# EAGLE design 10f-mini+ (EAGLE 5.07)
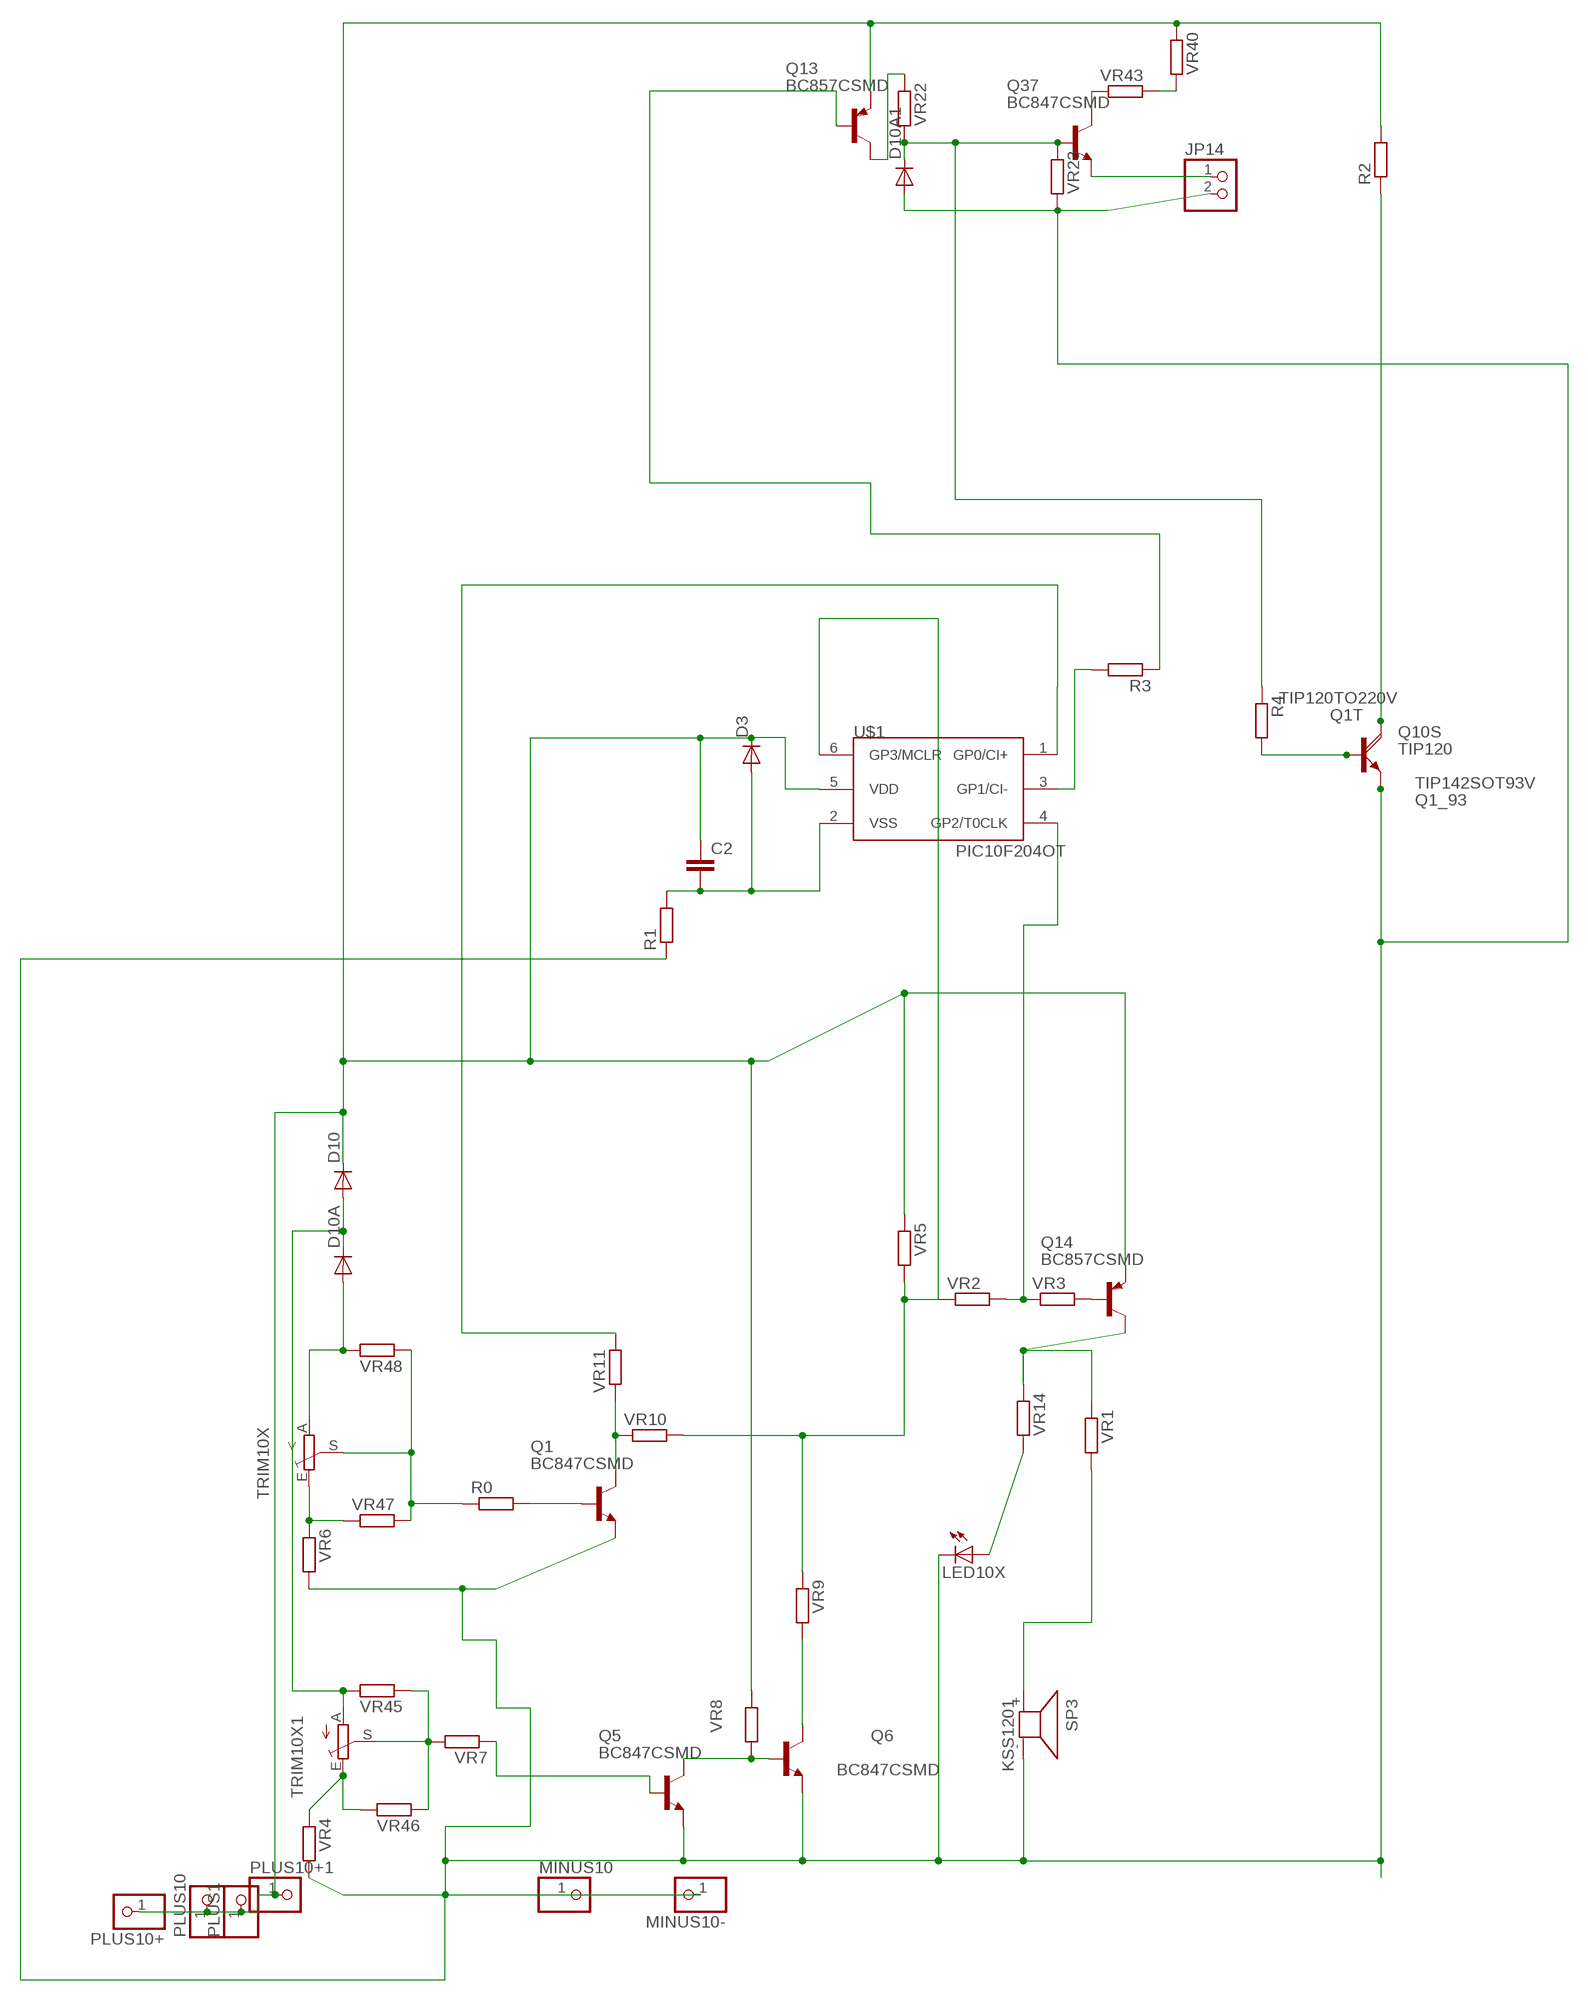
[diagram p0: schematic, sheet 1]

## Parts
C2  C-EUC0805  [C0805]
D3  DIODE-MINIMELF  [MINIMELF]
D10  DIODE-MINIMELF  [MINIMELF]
D10A  DIODE-MINIMELF  [MINIMELF]
D10A1  DIODE-MINIMELF  [MINIMELF]
JP14  PINHD-1X2STR  [1X02]
LED10X  LEDCHIPLED_1206  [CHIPLED_1206]
MINUS10  PINHD-1X14.5MM  [1X4MM5]
MINUS10-  PINHD-1X11X0.4  [1X01]
PLUS1  PINHD-1X14.5MM  [1X4MM5]
PLUS10  PINHD-1X14.5MM  [1X4MM5]
PLUS10+  PINHD-1X11X0.4  [1X01]
PLUS10+1  PINHD-1X11X0.4  [1X01]
Q1  BC847CSMD  [SOT23]
Q1_93  TIP142SOT93V  [SOT93V]
Q1T  TIP120TO220V  [TO220AV]
Q5  BC847CSMD  [SOT23]
Q6  BC847CSMD  [SOT23]
Q10S  TIP120  TIP120DPAK  [D-PAK_TO252AA]
Q13  BC857CSMD  [SOT23-BEC]
Q14  BC857CSMD  [SOT23-BEC]
Q37  BC847CSMD  [SOT23]
R0  R-EU_R1206  [R1206]
R1  R-EU_R0805  [R0805]
R2  R-EU_CERAM85  [CERAM85]
R3  R-EU_R0805  [R0805]
R4  R-EU_R0805  [R0805]
SP3  KSS1201  KSS12017MM  [KSS1202]
TRIM10X  TRIM_EU-S64W  [S64W]
TRIM10X1  TRIM_EU-S64W  [S64W]
U$1  PIC10F204OT  [SOT23-6]
VR1  R-EU_R0805  [R0805]
VR2  R-EU_R0805  [R0805]
VR3  R-EU_R1206  [R1206]
VR4  R-EU_R1206  [R1206]
VR5  R-EU_R0805  [R0805]
VR6  R-EU_R1206  [R1206]
VR7  R-EU_M1206  [M1206]
VR8  R-EU_R1206  [R1206]
VR9  R-EU_R0805  [R0805]
VR10  R-EU_R1206  [R1206]
VR11  R-EU_R0805  [R0805]
VR14  R-EU_R0805  [R0805]
VR22  R-EU_R0805  [R0805]
VR23  R-EU_R0805  [R0805]
VR40  R-EU_R1206  [R1206]
VR43  R-EU_R1206  [R1206]
VR45  R-EU_R0805  [R0805]
VR46  R-EU_R1206  [R1206]
VR47  R-EU_R0805  [R0805]
VR48  R-EU_R0805  [R0805]

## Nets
B: R0.1 TRIM10X.S VR47.2 VR48.1
BUZZ+: SP3.+ VR1.2
GP3: U$1.4(GP2/T0CLK) VR2.2 VR3.1
N$1: R3.2 U$1.3(GP1/CI-)
N$2: Q1.3(C) VR10.1 VR11.1
N$3: Q5.3(C) Q6.1(B) VR8.2
N$4: LED10X.A VR14.2
N$5: Q6.3(C) VR9.2
N$6: U$1.6(GP3/MCLR) VR2.1 VR5.2 VR9.1 VR10.2
N$7: Q1.1(B) R0.2
N$8: Q14.C VR1.1 VR14.1
N$10: Q14.B VR3.2
N$14: D10A.A TRIM10X.A VR48.2
N$17: D10.A D10A.C TRIM10X1.A VR45.2
N$22: TRIM10X1.S VR7.2 VR45.1 VR46.1
N$23: Q13.B R3.1
N$24: TRIM10X1.E VR4.1 VR46.2
N$25: Q1_93.B Q1T.B Q10S.1(B) R4.2
N$128: TRIM10X.E VR6.1 VR47.1
N$136: JP14.1 Q37.2(E)
N$138: U$1.1(GP0/CI+) VR11.2
N$159: Q13.C VR22.1
N$163: VR40.2 VR43.2
N$164: Q37.3(C) VR43.1
N$168: Q5.1(B) VR7.1
N$179: D10A1.C Q37.1(B) R4.1 VR22.2 VR23.1
PLUS1: C2.1 D3.C D10.C PLUS1.1 PLUS10+1.1 PLUS10+.1 PLUS10.1 Q13.E Q14.E R2.2 U$1.5(VDD) VR5.1 VR8.1 VR40.1
Q10C: Q1_93.C Q1T.C Q10S.4(C) R2.1
VSS: D10A1.A JP14.2 LED10X.C MINUS10-.1 MINUS10.1 Q1.2(E) Q1_93.E Q1T.E Q5.2(E) Q6.2(E) Q10S.3(E) R1.1 SP3.- VR4.2 VR6.2 VR23.2
VSS1: C2.2 D3.A R1.2 U$1.2(VSS)

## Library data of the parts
C2 = rcl:C-EU: CAPACITOR, European symbol
D3 D10 D10A D10A1 = diode:DIODE-: DIODE
JP14 = pinhead:PINHD-1X2: PIN HEADER
LED10X = led:LED: LED
MINUS10 MINUS10- PLUS1 PLUS10 PLUS10+ PLUS10+1 = pinhead:PINHD-1X1: PIN HEADER
Q1 Q5 Q6 Q37 = transistor-npn:BC847*: NPN Transistor
Q1_93 = transistor-power:TIP142: NPN DARLINGTON TRANSISTOR
Q1T Q10S = transistor-power:TIP120: NPN DARLINGTON TRANSISTOR
Q13 Q14 = transistor-pnp:BC857*: PNP Transistror
R0 R1 R3 R4 VR1-VR11 VR14 VR22 VR23 VR40 VR43 VR45-VR48 = rcl-2:R-EU_: RESISTOR, European symbol
R2 = rcl:R-EU_: RESISTOR, European symbol
SP3 = buzzer:KSS1201: SPEAKER
TRIM10X TRIM10X1 = pot:TRIM_EU-: POTENTIOMETER
U$1 = microchip-3:PIC10F2*: uPC nW 0,25/0,5k Program Flash memory Comparator

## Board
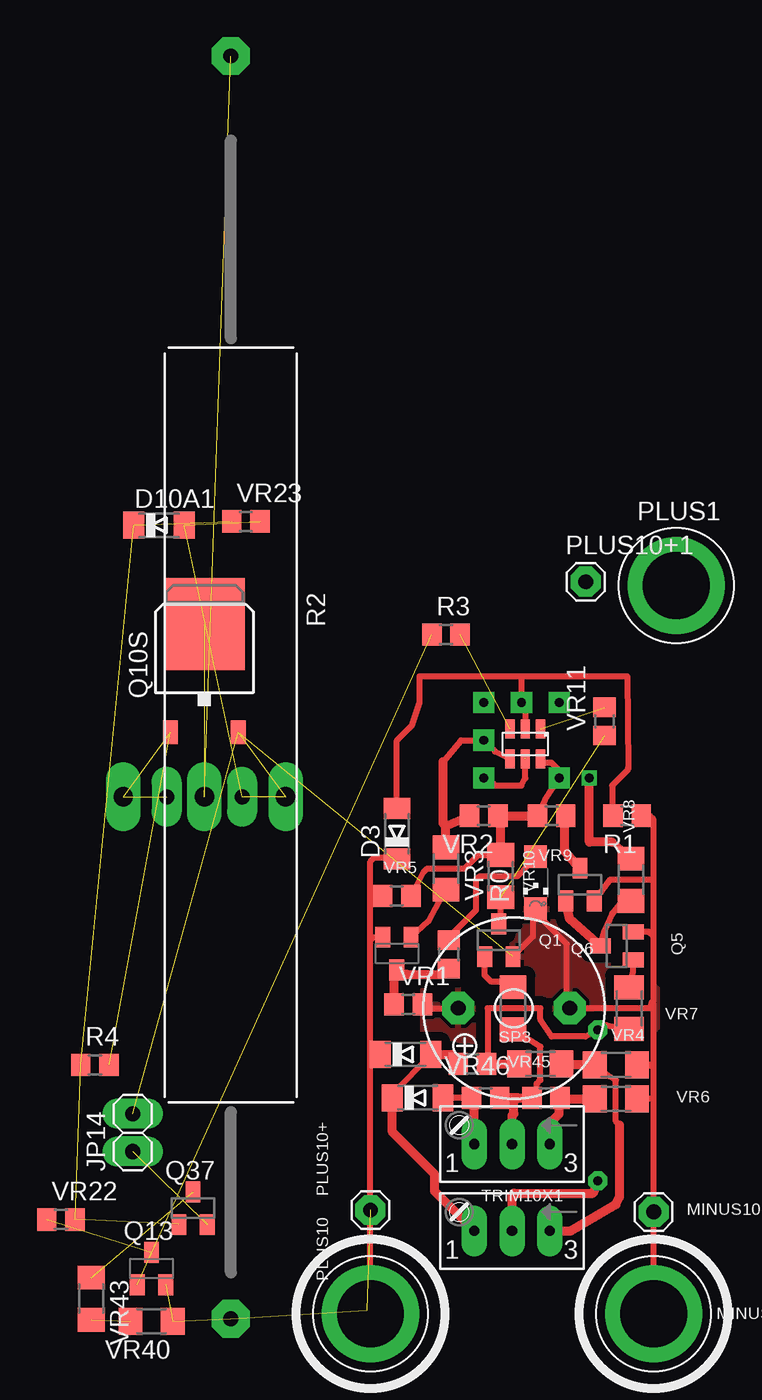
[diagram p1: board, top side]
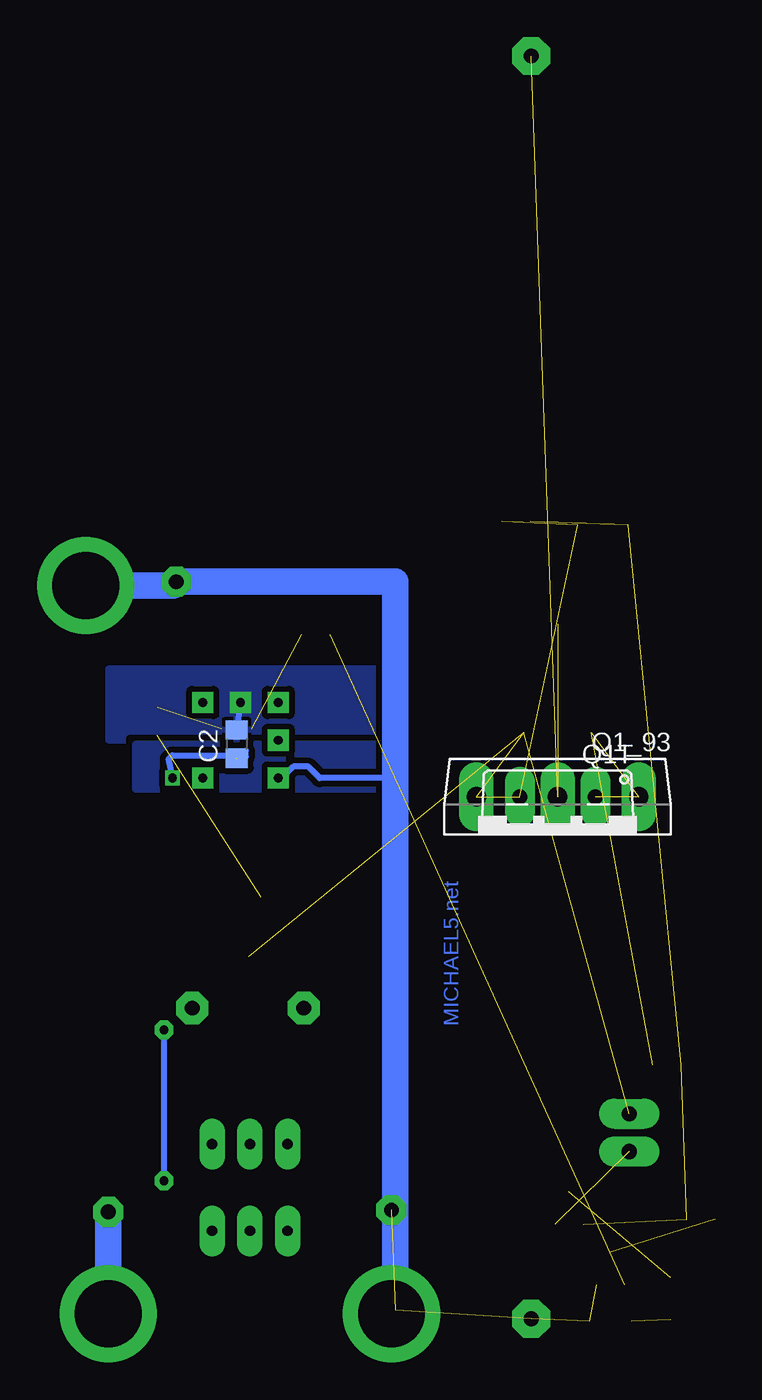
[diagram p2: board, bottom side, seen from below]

No outline drawn. Coordinates in mm, seen from the top.
Copper layers (1*16): Top 0.035mm / dielectric 1.5mm / Bottom 0.035mm
Design rules "default *": minimum track width 8mil, minimum drill 4mil, track to track 8mil, track to pad 8mil, pad to pad 8mil, via to via 8mil, smd to smd 8mil, copper to edge 40mil, drill to drill 8mil, minimum pad ring 20mil, minimum via ring 8mil, stop-mask expansion 4mil, vias tented up to drill 0mil, thermal gap 10mil

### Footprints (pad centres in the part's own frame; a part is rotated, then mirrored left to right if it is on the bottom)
C0805 = smd 1.3 x 1.5: 1 -0.95,0; 2 0.95,0
MINIMELF = smd 1.4 x 1.8: A 1.7,0; C -1.7,0
1X02 = drill 1.016 pad 1.676 long: 1 -1.27,0; 2 1.27,0
CHIPLED_1206 = smd 1.5 x 1.5: A 0,-1.75; C 0,1.75
1X4MM5 = drill 4.5 pad 6.35 round: 1 0,0
1X01 = drill 1 pad 1.676 octagon: 1 0,0
SOT23 = smd 1 x 1.4: 1 -0.95,-1.1; 2 0.95,-1.1; 3 0,1.1
SOT93V = drill 1.3 pad 1.676 long: B -5.461,-2.54; C 0,-2.54; E 5.461,-2.54
TO220AV = drill 1 pad 1.27 long: B -2.54,-2.54; C 0,-2.54; E 2.54,-2.54
D-PAK_TO252AA = smd 1 x 1.6: 1 -2.28,-4.8; 3 2.28,-4.8 | smd 5.4 x 6.2: 4 0,2.5
SOT23-BEC = smd 1 x 1.4: B -0.95,-1.1; C 0,1.1; E 0.95,-1.1
R1206 = smd 1.6 x 1.803: 1 -1.422,0; 2 1.422,0
R0805 = smd 1.3 x 1.5: 1 -0.95,0; 2 0.95,0
CERAM85 = drill 1 pad 2.54 octagon: 1 -42.5,0; 2 42.5,0
KSS1202 = drill 1 pad 2.159 octagon: + 3.75,0; - -3.75,0
S64W = drill 0.7 long: A 2.54,1.27; E -2.54,1.27; S 0,1.27
SOT23-6 = smd 0.635 x 1.27: 1 -1.016,-1.016; 2 0,-1.016; 3 1.016,-1.016; 4 1.016,1.016; 5 0,1.016; 6 -1.016,1.016
M1206 = smd 1.6 x 2: 1 -1.4,0; 2 1.4,0

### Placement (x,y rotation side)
C2  81.53,47.24 90 bottom
D3  72.9,41.21 90 top
D10  73.47,26.35 0 top
D10A  74.3,23.43 0 top
D10A1  56.9,61.98 0 top
JP14  55.12,21.08 90 top
LED10X  82.23,37.91 180 top
MINUS10  90.17,8.89 0 top
MINUS10-  90.17,15.75 0 top
PLUS1  91.69,57.91 0 top
PLUS10  71.12,8.89 0 top
PLUS10+  71.12,15.88 0 top
PLUS10+1  85.6,58.17 0 top
Q1  79.76,34.04 0 top
Q1_93  59.94,41.15 180 bottom
Q1T  59.94,41.15 180 bottom
Q5  87.69,33.66 90 top
Q6  85.22,37.78 0 top
Q10S  59.94,52.83 0 top
Q13  56.39,11.94 0 top
Q14  72.9,33.15 180 top
Q37  59.18,16 0 top
R0  80.71,29.46 90 top
R1  88.39,42.42 180 top
R2  61.72,51.05 270 top
R3  76.2,54.61 0 top
R4  52.58,25.65 0 top
SP3  80.77,29.46 180 top
TRIM10X  80.64,21.59 180 top
TRIM10X1  80.64,15.75 180 top
U$1  81.53,47.24 180 top
VR1  73.66,29.72 0 top
VR2  78.74,42.42 180 top
VR3  76.2,38.86 270 top
VR4  87.63,25.65 0 top
VR5  72.9,37.02 0 top
VR6  87.63,23.37 0 top
VR7  88.52,29.46 270 top
VR8  88.65,38.1 270 top
VR9  83.31,42.42 0 top
VR10  79.88,38.35 90 top
VR11  86.87,48.77 90 top
VR14  76.39,33.08 90 top
VR22  50.29,15.24 0 top
VR23  62.74,62.23 0 top
VR40  56.39,8.38 180 top
VR43  52.32,9.91 270 top
VR45  77.98,25.72 180 top
VR46  82.55,25.72 0 top
VR47  82.93,23.43 180 top
VR48  78.87,23.43 180 top

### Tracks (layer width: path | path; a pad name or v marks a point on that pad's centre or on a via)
B
  Top 0.406: VR47.2 82.3,23.75 82.3,24.38 82.55,24.64 82.55,26.86 R0.1 | 80.64,22.23 80.77,22.35
  Top 0.61: 81.03,23.43 VR48.1 | 81.03,23.43 VR47.2 | TRIM10X.S 80.64,22.23 | 80.77,22.35 80.77,23.18 81.03,23.43
BUZZ+
  Top 0.406: SP3.+ 74.86,29.46 VR1.2
  pour Top (isolate 0.61): 75.44,31.24 78.99,31.24 79.5,30.73 79.5,27.18 79.25,26.92 75.44,26.92 74.68,27.69 74.68,30.73
GP3  (via drill 0.6 pad 1.42)
  Top 0.406: U$1.4 79.5,46.74 v78.74,47.5 77.22,47.5 76.01,46.04
  Top 0.61: VR3.1 76.2,41.72 | 76.2,41.72 VR2.2 | 76.01,46.04 76.01,41.91 76.2,41.72
N$1  (1 unrouted)
N$2  (1 unrouted)
  Top 0.406: VR10.1 79.88,35.26 Q1.3
N$3
  Top 0.406: VR8.2 88.49,37.19 87.38,35.81 86.87,34.69 Q5.3
  Top 0.61: Q6.1 84.52,35.47 Q5.3
N$4
  Top 0.406: VR14.2 76.39,34.23 78.23,36.07 78.23,38.1 78.49,38.35 81.03,38.35 81.28,38.61 81.79,39.22 LED10X.A
N$5
  Top 0.406: 84.58,42.23 VR9.2
  Top 0.61: Q6.3 84.2,40.01 84.2,42.16 84.58,42.23
N$6
  Top 0.406: VR9.1 82.87,43.5 83.82,44.96 83.82,45.47 83.31,45.97 82.8,45.97 U$1.6 | VR10.2 78.38,39.78 77.47,38.86 74.93,38.86 74.68,38.61 74.17,37.59 VR5.2 | 79.88,42.23 VR2.1
  Top 0.61: VR2.1 VR9.1 | VR10.2 79.88,42.23
N$7
  Top 0.406: Q1.1 78.81,31.68 79.25,31.24 80.35,31.24 R0.2
N$8
  Top 0.406: 75.95,31.75 76.33,32.13 VR14.1 | 73.55,31.75 Q14.C 72.71,31.86
  Top 0.61: 73.55,31.75 75.95,31.75 | VR1.1 72.71,31.86
N$9  (via drill 0.6 pad 1.42)
  other vias: 83.82,44.96
N$10
  Top 0.406: Q14.B 75.04,35.33 VR3.2
N$11  (via drill 0.6 pad 1.42)
  other vias: 83.82,50.04
N$14
  Top 0.406: 78.11,23.37 VR48.2 D10A.A
  Top 0.61: TRIM10X.A 78.11,23.37
N$17
  Top 0.406: 76.58,26.35 VR45.2 | D10A.C 72.59,23.65 D10.A
  Top 0.61: D10.A 76.58,26.35 | D10A.C 72.59,21.13 75.44,18.29 75.44,17.14 TRIM10X1.A
N$22  (via drill 0.6 pad 1.27)
  Top 0.406: VR45.1 78.99,25.72 78.99,29.46 82.55,29.46 82.55,28.7 83.31,27.56 85.6,27.56 v86.42,28 86.99,28.32 VR7.2 | 80.64,16.89 80.77,17.02
  Top 0.61: 78.99,25.72 VR46.1 | TRIM10X1.S 80.64,16.89 | 80.77,17.02 86.11,17.02 v86.42,17.84
  Bottom 0.406: v86.42,17.84 v86.42,28
N$23  (1 unrouted)
N$24
  Top 0.406: 87.88,21.59 87.63,21.84 87.63,24.64 87.12,24.89 86.46,25.4 VR4.1 | 84.03,25.65 VR46.2
  Top 0.61: TRIM10X1.E 84.58,14.48 87.63,16.26 87.88,16.76 87.88,21.59 | VR4.1 84.03,25.65
N$25  (3 unrouted)
N$128
  Top 0.406: 83.82,23.37 VR47.1 83.82,23.37
  Top 0.61: TRIM10X.E 83.19,21.72 83.82,22.35 83.82,23.37 | 83.82,23.37 VR6.1
N$136  (1 unrouted)
N$138  (1 unrouted)
N$159  (1 unrouted)
N$163  (1 unrouted)
N$164  (1 unrouted)
N$168
  Top 0.406: Q5.1 88.79,31.9 VR7.1
N$179  (4 unrouted)
PLUS1  (via drill 0.6, 0.6 pad 1.42)  (5 unrouted)
  Top 0.406: PLUS10.1 71.12,26.35 | 71.12,26.35 D10.C | 71.12,26.35 71.12,34.04 | D3.C 72.78,39.62 71.37,39.62 71.12,39.33 71.12,37.08 | 71.12,34.04 71.12,37.08 | Q14.E 71.33,34.25 71.12,34.04 | VR5.1 71.18,37.02 71.12,37.08 | U$1.5 81.53,44.96 81.28,44.45 79.5,44.45 78.99,44.96 v78.74,44.96 | VR8.1 88.24,40.03 87.38,40.64
  Top 0.61: 87.38,40.64 85.85,40.64 v85.85,44.96
  Bottom 0.406: C2.1 80.91,46.8 80.91,46.4 81.03,46.4 81.03,46.48 85.85,46.48 86.11,46.23 v85.85,44.96 | v78.74,44.96 78.49,44.96 77.72,45.72 76.71,45.72 75.95,44.96 71.12,44.96 70.87,44.7
  Bottom 1.778: PLUS10.1 70.87,9.14 70.87,44.7 70.87,58.17 PLUS10+1.1 85.85,57.91 PLUS1.1
PLUS11
  pour Bottom (isolate 0.406): 70.61,47.24 88.39,47.24 88.39,44.2 70.87,44.2
Q10C  (3 unrouted)
VDF  (via drill 0.6 pad 1.42)
  other vias: 78.74,50.04
VSS  (6 unrouted)
  Top 0.406: MINUS10.1 90.17,23.37 | 90.17,23.37 90.17,25.4 | VR4.2 89.92,25.65 90.17,25.4 | 90.17,23.37 VR6.2 | 90.04,29.84 90.17,29.72 90.17,25.4 | 90.04,29.84 89.92,29.46 SP3.- 84.33,29.66 84.33,33.78 82.23,35.88 LED10X.C 82.04,35.97 82.04,34.29 80.71,32.95 Q1.2 | Q5.2 89.86,34.6 90.17,34.29 | 90.17,34.29 90.17,29.97 90.04,29.84 | R1.1 89.92,42.42 90.17,42.16 90.17,38.1 | 90.17,34.29 90.17,38.1 | Q6.2 87.23,38.1 90.17,38.1
  Bottom 1.778: MINUS10.1 MINUS10-.1
  pour Top (isolate 0.61): 81.53,36.83 81.53,34.8 80.52,33.78 80.52,32 84.58,27.94 90.17,27.94 90.42,28.19 90.42,30.73 89.66,31.5 87.12,31.5 87.12,34.29 85.6,35.05
VSS1  (via drill 0.6 pad 1.42)
  Top 0.406: 81.28,51.82 74.42,51.82 74.42,50.04 73.91,48.51 72.9,47.5 D3.A | U$1.2 81.53,49.47 v81.28,50.04 81.28,51.82 | 87.38,42.61 87.38,44.45 88.46,45.53 88.46,45.65 88.39,51.82 81.28,51.82
  Top 0.61: 87.38,42.61 R1.2
  Bottom 0.406: v81.28,50.04 C2.2
  pour Bottom (isolate 0.406, rank 2): 72.14,52.32 90.17,52.32 90.17,47.5 72.14,47.5

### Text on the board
Bottom: MICHAEL5.net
